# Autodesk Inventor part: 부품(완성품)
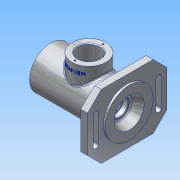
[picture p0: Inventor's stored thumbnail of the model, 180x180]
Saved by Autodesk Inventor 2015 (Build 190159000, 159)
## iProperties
Created: 2017-10
Part Number: 부품(완성품)
Material: 알루미늄 6061
Document SubType Name: Modeling
Designer: Administrator
Density: 2.7 g/cm^3
Appearance: 알루미늄 - 평지
Mass: 738.166 g
Surface Area: 653.383 cm^2
Volume: 273.395 cm^3
Author: Administrator
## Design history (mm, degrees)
sketch "스케치1"
  geometry: L1 (58, 27)-(58, -27); L2 (38, -47)-(-38, -47); L3 (38, 47)-(-38, 47); L4 (-58, -27)-(-58, 27); L5 (-38, 47)-(-58, 27); L6 (58, 27)-(38, 47); L7 (58, -27)-(38, -47); L8 (-38, -47)-(-58, -27); 7 further points
  constraints: 16 end point, 8 point on line, 2 midpoint, 1 horizontal, 1 horizontal alignment, 1 perpendicular, 1 vertical, 1 vertical alignment
  dimensions: "d6" = 20 distance of L3.end point (-58, 47); "d7" = 20 distance of L4.end point (-58, 47) (= d6); "d8" = 20 distance of L1.start point (58, 47) (= d6); "d9" = 20 distance of L3.start point (58, 47) (= d8); "d10" = 20 distance of L1.end point (58, -47) (= d6); "d11" = 20 distance of L2.start point (58, -47) (= d10); "d12" = 20 distance of L2.end point (-58, -47) (= d6); "d13" = 20 distance of L4.start point (-58, -47) (= d12); "d14" = 116 distance between parallel lines of L1 L4; "d15" = 94 distance between parallel lines of L2 L3
extrude "돌출1" new body sketch "스케치1" distance "d16" = 10; taper "d17" = 0 deg
sketch "스케치2"
  geometry: C1 r 35 at (0, 0); 1 further point
  constraints: 1 centre point, 1 coincident
  dimensions: "d18" = 70 diameter of C1
extrude "돌출2" join sketch "스케치2" distance "d19" = 3; taper "d20" = 0 deg
sketch "스케치3"
  geometry: L1 (13, -35)-(13, 35) reference; L2 (13, 0)-(-102, 0); L3 (0, 27)-(0, 47) reference; L4 (0, -27)-(0, 27) reference; L5 (-102, 31)-(-102, 0); L6 (-102, 31)-(13, 31); 1 further point
  constraints: 6 end point, 1 horizontal, 1 midpoint, 1 perpendicular, 1 point on line
  dimensions: "d21" = 115 distance of L2.start L2.end; "d22" = 62 diameter of L6 L2; "d23" = 115 distance of L5.start L6.end
revolve "회전1" sketch "스케치3" stored, may be unused: angle "d24" = 90 deg
sketch "스케치5"
  geometry: L1 (31, -102)-(-31, -102) reference; C1 r 25 at (0, -46); 1 further point
  constraints: 1 centre point, 1 vertical alignment
  dimensions: "d27" = 50 diameter of C1; "d28" = 56 distance from line of C1.centre L1
extrude "돌출3" join sketch "스케치5" distance "d29" = 47; taper "d30" = 0 deg
hole "구멍1" diameter "d33" = 40.376; stored, may be unused: countersink angle "d37" = 90 deg, drill point angle "d39" = 0 deg; dims "d31" = 10, "d32" = 10, "d34" = 9, "d35" = 4, "d36" = 2, "d38" = 9
sketch "스케치6"
  geometry: L1 (-93, 20.188)-(-93, -20.188) reference; L2 (13, -35)-(13, 35) reference; L3 (-93, 0)-(13, 0); L4 (-93, 0)-(-93, 24); L5 (-93, 24)-(-90, 24); L6 (-90, 24)-(-90, 20); L7 (-81, 20)-(-81, 17.5); L8 (-81, 17.5)-(-77.75, 17.5); L9 (-77.75, 17.5)-(-77.75, 18.5); L10 (-77.75, 18.5)-(-76, 18.5); L11 (-76, 18.5)-(-76, 17.5); L12 (-76, 17.5)-(-65, 17.5); L13 (-65, 17.5)-(-65, 23); L14 (-62, 26)-(-30, 26); L15 (-102, -20.188)-(-102, 20.188) reference; L16 (-27, 23)-(-27, 17.5); L17 (-27, 17.5)-(-16, 17.5); L18 (-16, 17.5)-(-16, 0); L19 (-90, 20)-(-81, 20); A1 r 3 centre (-62, 23) between (-62, 26) and (-65, 23); A2 r 3 centre (-30, 23) between (-27, 23) and (-30, 26); 3 further points
  constraints: 32 end point, 9 perpendicular, 8 point on line, 4 point on circle, 4 tangent, 2 centre point, 2 midpoint, 1 collinear, 1 equal radius, 1 horizontal, 1 vertical
  dimensions: "d40" = 3 distance of L4.end L5.end; "d41" = 21 distance from line of L7.start L15; "d42" = 26 distance from line of L11.end L15; "d44" = 1.75 distance of L9.end L10.end; "d45" = 60 horizontal distance of L17.end L10.end; "d46" = 38 distance of point (-65, 26) point (-27, 26); "d48" = 37 diameter of L10 L3; "d49" = 40 diameter of L19 L3; "d50" = 35 diameter of L8 L3; "d51" = 48 diameter of L5 L3; "d52" = 35 diameter of L17 L3; "d53" = 52 diameter of L14 L3; "d55" = 3 radius of A1
revolve "회전2" sketch "스케치6" stored, may be unused: angle "d54" = 90 deg
sketch "스케치7"
  geometry: L1 (-16, 17.5)-(-16, -17.5) reference; L2 (13, -35)-(13, 35) reference; L3 (13, 0)-(-16, 0); L4 (-16, 16.5)-(-14, 16.5); L5 (-11, 13.5)-(-11, 10); L6 (-11, 10)-(-8.3, 10); L7 (-8.3, 10)-(-8.3, 12.2); L8 (-8, 12.5)-(-1.7, 12.5); L9 (-1, 12.904)-(-1, 14.022); L10 (0.818, 16.779)-(13, 22); L11 (-16, 16.5)-(-16, 0); L12 (-1.7, 12.5)-(-1, 12.904); L13 (13, 22)-(13, 0); A1 r 3 centre (-14, 13.5) between (-11, 13.5) and (-14, 16.5); A2 r 0.3 centre (-8, 12.2) between (-8, 12.5) and (-8.3, 12.2); A3 r 3 centre (2, 14.022) between (0.818, 16.779) and (-1, 14.022); 5 further points
  constraints: 22 end point, 10 point on line, 6 point on circle, 6 tangent, 5 perpendicular, 3 centre point, 2 collinear, 2 midpoint, 1 horizontal
  dimensions: "d56" = 14 horizontal distance of point (-1, 16) L10.end; "d57" = 5 distance of L4.start point (-11, 16.5); "d58" = 32 diameter of point (-1, 16) L3; "d59" = 44 diameter of L10.end L3; "d60" = 7.3 distance of point (-8.3, 12.5) point (-1, 12.5); "d61" = 20 diameter of L6 L3; "d62" = 25 diameter of L8 L3; "d63" = 33 diameter of L4 L3; "d64" = 3 radius of A1; "d65" = 0.3 radius of A2; "d66" = 0.7 distance of L8.end point (-1, 12.5); "d67" = 30 deg angle of L8 L12; "d68" = 3 radius of A3
revolve "회전3" sketch "스케치7" stored, may be unused: angle "d69" = 90 deg
fillet "모깎기1" dims "d73" = 0.3
sketch "스케치8"
  geometry: L1 (-102, -31)-(-102, 31) reference; L2 (-21, 47)-(-71, 47) reference; 2 further points
  constraints: 1 other
  dimensions: "d74" = 56 distance from line of point (-46, 37) L1; "d75" = 10 distance from line of point (-46, 37) L2
feature "엠보싱1" sketch "스케치8" dims "d76" = 0.5, "d77" = 0
hole "구멍2" diameter "d80" = 32; stored, may be unused: countersink angle "d84" = 90 deg, drill point angle "d86" = 0 deg; dims "d78" = 10, "d79" = 10, "d81" = 9, "d82" = 4, "d83" = 2, "d85" = 47
sketch "스케치9" dims "d87" = 41
  geometry: 4 further points
  constraints: 2 horizontal alignment, 1 vertical alignment, 3 other
hole "구멍3" sketch "스케치9" at (-20.5, 0) diameter "d88" = 2.459; stored, may be unused: countersink angle "d92" = 90 deg, drill point angle "d94" = 118 deg; dims "d89" = 6, "d90" = 4, "d91" = 2, "d93" = 8
sketch "스케치10"
  geometry: L1 (50, -20)-(50, 20); L2 (42, 20)-(42, -20); L3 (-42, -20)-(-42, 20); L4 (-50, -20)-(-50, 20); L5 (38, -47)-(58, -27) reference; L6 (-38, -47)-(38, -47) reference; L7 (-58, -27)-(-38, -47) reference; L8 (-58, 27)-(-58, -27) reference; L9 (-38, 47)-(-58, 27) reference; L10 (38, 47)-(-38, 47) reference; L11 (58, 27)-(38, 47) reference; L12 (58, -27)-(58, 27) reference; C1 r 31 at (0, 0) reference; A1 r 4 centre (46, 20) between (50, 20) and (42, 20); A2 r 4 centre (46, -20) between (42, -20) and (50, -20); A3 r 4 centre (-46, 20) between (-42, 20) and (-50, 20); A4 r 4 centre (-46, -20) between (-50, -20) and (-42, -20); 3 further points
  constraints: 8 end point, 8 point on circle, 6 tangent, 4 centre point, 4 vertical, 2 equal radius, 2 horizontal alignment, 2 midpoint, 2 parallel
  dimensions: "d99" = 46 horizontal distance of point (0, 0) A1.centre; "d100" = 4 radius of A4; "d101" = 92 distance of A3.centre A1.centre; "d102" = 40 distance of A3.centre A4.centre
extrude "돌출4" cut sketch "스케치10" distance "d104" = 47; taper "d105" = 0 deg
fillet "모깎기2" dims "d109" = 3
chamfer "모따기3" distance "d110" = 1; stored, may be unused: second distance "d111" = 2, angle "d112" = 45 deg
chamfer "모따기4" distance "d113" = 1; stored, may be unused: second distance "d114" = 2, angle "d115" = 45 deg
chamfer "모따기5" distance "d116" = 1; stored, may be unused: second distance "d117" = 2, angle "d118" = 45 deg
node "솔리드1"
pattern_circular "원형 패턴1" dims angle "d96" = 360 deg
node "투영된 루프1"
